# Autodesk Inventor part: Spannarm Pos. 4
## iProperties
Created: 2009-11
Part Number: Spannarm Pos. 4
Document SubType Name: Modeling
Designer: user
Author: user
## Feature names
1. Extrusion1
2. Extrusion2
3. Extrusion3
4. Extrusion4
5. Extrusion5
6. Extrusion6
7. Bohrung1 [Hole]
8. Bohrung2 [Hole]
9. Bohrung3 [Hole]
10. Bohrung4 [Hole]
11. Rundung1 [Fillet]
12. Fase1 [Chamfer]
